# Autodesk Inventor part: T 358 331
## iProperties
Created: 2005-11
Part Number: T 358 331
Material: 1.0718.07
Description: Buchse
Vendor: Autodesk Inc.
Document SubType Name: Modeling
Standard: DIN 671
Designer: I.Baliuc
Size Designation: 10 - 53
Density: 7.84 g/cm^3
Abmessung: Rd 70 - 10
Zweck: Seitenteil / Vorkontakt HSLT
Author: T.Messerschmitt
Revision Number: 358331
Comments: DIN 671 / Rd 70 - 15
Keywords: 266474
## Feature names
1. Körper [Extrusion]
2. Bohrung1 [Hole]
